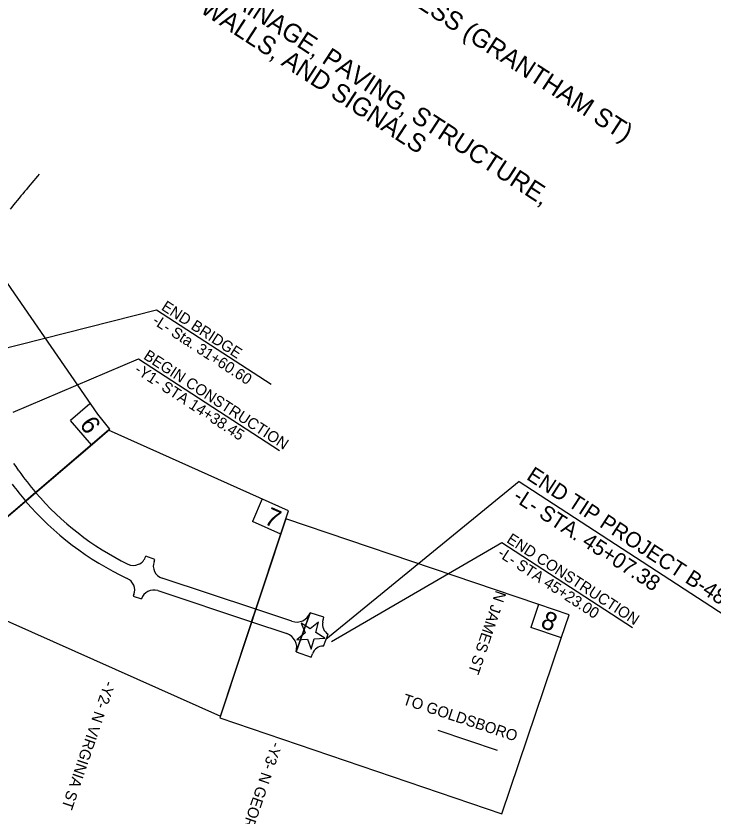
# Model space of a CAD drawing. Extents: x 2291197 to 2302790, y 592892 to 604246.
# Drawn here: x 2298300 to 2300199, y 598987 to 601165 of the extents above; entities that cross this region are included whole.
import ezdxf

# ---------------------------------------------------------------- set-up
doc = ezdxf.new("R2010")
doc.units = 0
for name, color, linetype in [('Exist Railroads Standard Gauge', 7, 'Continuous'), ('Prop DSN Text', 7, 'Continuous'), ('Prop Horizontal Alignment Station Label', 7, 'Continuous'), ('Prop RDY Traffic Signal CELL', 7, 'Continuous'), ('Prop Shade Light', 7, 'Continuous'), ('Sheet Data Field CELL', 7, 'Continuous')]:
    doc.layers.add(name, color=color, linetype=linetype)

msp = doc.modelspace()

# ---------------------------------------------------------------- linework, layer by layer
at = {"layer": 'Exist Railroads Standard Gauge'}
msp.add_arc((2302270.8, 597407.9), 5131.8, 139.5841, 140.9746, dxfattribs=at)
at = {"layer": 'Prop DSN Text'}
for p, q in [((2298501.3, 600109.3), (2298448.5, 600064.3)), ((2298505.6, 599997.3), (2298448.5, 600064.3)), ((2298971.3, 599850.2), (2298944.2, 599789.3)), ((2299021.6, 599754.7), (2298944.2, 599789.3)), ((2299723.9, 599562.7), (2299702.7, 599500.3)), ((2299786, 599472), (2299702.7, 599500.3)), ((2299611.7, 599164.8), (2299450, 599220))]:
    msp.add_line(p, q, dxfattribs=at)
for points in [[(2297647.4, 600347.7), (2298116.9, 599666), (2298116.9, 599666), (2298502, 599994.3), (2298556.3, 600040.5), (2298523, 600081.3), (2298287.2, 600423.6), (2298114.3, 600674.7)], [(2298166.7, 599708.4), (2298114.1, 599590.5), (2298857, 599258.9), (2299007.3, 599711.6), (2299042.7, 599818.3), (2298552.3, 600037.2)], [(2299035.5, 599796.5), (2298855.4, 599254), (2299623.4, 598993.2), (2299785.7, 599471.3), (2299807.2, 599534.4), (2299807.5, 599535), (2299721.9, 599563.3)]]:
    msp.add_lwpolyline(points, close=True, dxfattribs=at)
at = {"layer": 'Prop Horizontal Alignment Station Label'}
for p, q in [((2298085.2, 600214), (2298683, 600365.2)), ((2298683, 600365.2), (2298995, 600162.4)), ((2298292.2, 600086.9), (2298634.3, 600231.7)), ((2298634.3, 600231.7), (2299018.2, 599982.1)), ((2299671.3, 599897.4), (2299144.7, 599467.3)), ((2299671.3, 599897.4), (2300373.2, 599441.1)), ((2299159.6, 599462.4), (2299623.6, 599731.9)), ((2299623.6, 599731.9), (2299979.9, 599500.3))]:
    msp.add_line(p, q, dxfattribs=at)
at = {"layer": 'Prop RDY Traffic Signal CELL'}
msp.add_lwpolyline([(2299087.9, 599485.3), (2299065.3, 599467), (2299094.3, 599468.5), (2299104.7, 599441.4), (2299112.2, 599469.5), (2299141.2, 599471), (2299116.9, 599486.8), (2299124.4, 599514.8), (2299101.8, 599496.6), (2299077.4, 599512.4), (2299087.9, 599485.3)], dxfattribs=at)
at = {"layer": 'Prop Shade Light'}
for p, q in [((2298353.8, 599867.9), (2298326.4, 599844.6)), ((2298326.4, 599844.6), (2298353.8, 599867.9)), ((2298678.4, 599685.1), (2298653.9, 599694.2)), ((2298676.5, 599679.9), (2298678.4, 599685.1)), ((2298953.6, 599549.7), (2298698.2, 599634.5)), ((2298686.3, 599600.5), (2298942.3, 599515.6)), ((2298621.5, 599590.1), (2298619.9, 599585.7)), ((2298619.9, 599585.7), (2298642, 599578.1)), ((2298953.6, 599549.7), (2298942.3, 599515.6)), ((2298942.3, 599515.6), (2298953.6, 599549.7)), ((2299052.1, 599517), (2298953.6, 599549.7)), ((2299139, 599527.9), (2299102, 599540.3)), ((2298942.3, 599515.6), (2299037.7, 599483.9)), ((2299137.8, 599449.3), (2299150.5, 599482.3)), ((2299063.1, 599433.6), (2299104.8, 599419.6))]:
    msp.add_line(p, q, dxfattribs=at)
for points in [[(2298308.4, 599926.7), (2298300.3, 599938.2), (2298294, 599947.2)], [(2299063.1, 599433.6), (2299082.9, 599487.9), (2299102, 599540.3)], [(2299102, 599540.3), (2299082.9, 599487.9), (2299063.1, 599433.6)], [(2299136.3, 599515.1), (2299136.2, 599517.6), (2299137.7, 599523.8), (2299139, 599527.9)], [(2299104.8, 599419.6), (2299105.2, 599420.8), (2299108.3, 599428.9)]]:
    msp.add_lwpolyline(points, dxfattribs=at)
for centre, radius, start, end in [((2298948.9, 600375.3), 782, 215.0027, 220.4465), ((2298948.9, 600375.3), 818, 216.3618, 220.4465), ((2298948.9, 600375.3), 782, 220.4465, 243.913), ((2298948.9, 600375.3), 818, 220.4465, 245.0159), ((2298620.4, 599704.4), 35, 243.913, 343.1077), ((2298709.3, 599667.7), 35, 159.5745, 251.6371), ((2298588.6, 599602.1), 35, 339.9741, 65.0159), ((2298675.3, 599567.3), 35, 71.6371, 162.1209), ((2299064.7, 599555), 40, 251.6371, 338.4837), ((2299165.5, 599508.3), 30, 166.9415, 240.0259), ((2299025.1, 599445.9), 40, 342.0312, 71.6371), ((2299136.7, 599419.3), 30, 87.8938, 161.4979)]:
    msp.add_arc(centre, radius, start, end, dxfattribs=at)

# ---------------------------------------------------------------- texts
at = {"layer": 'Prop DSN Text'}
for s, height, rotation, p in [('6', 50, 304.5541, (2298471.8, 600053.4)), ('7', 50, 335.8394, (2298973.4, 599784)), ('N JAMES ST', 30, 251.0842, (2299608.1, 599602.7)), ('8', 50, 335.8394, (2299726.3, 599502.6)), ('-Y2- N VIRGINIA ST', 30, 251.0842, (2298542.6, 599356.7)), ('TO GOLDSBORO', 30, 341.6917, (2299351.6, 599291.8)), ('-Y3- N GEORGE ST', 30, 251.0842, (2298997.5, 599190.6))]:
    msp.add_text(s, height=height, rotation=rotation, dxfattribs=at).set_placement(p)
at = {"layer": 'Prop Horizontal Alignment Station Label'}
for s, height, p in [('END BRIDGE', 30, (2298694, 600367)), ('-L- Sta. 31+60.60', 30, (2298669.5, 600329.2)), ('BEGIN CONSTRUCTION', 30, (2298645.4, 600233.4)), ('-Y1- STA 14+38.45', 30, (2298620.9, 600195.7)), ('END TIP PROJECT B-4838', 42, (2299688.5, 599905.4)), ('-L- STA. 45+07.38', 42, (2299651.3, 599848.2)), ('END CONSTRUCTION', 30, (2299634.6, 599733.6)), ('-L- STA 45+23.00', 30, (2299610.1, 599695.9))]:
    msp.add_text(s, height=height, rotation=326.9737, dxfattribs=at).set_placement(p)
at = {"layer": 'Sheet Data Field CELL'}
for s, p in [('BRIDGE #950020 ON US 70 BUSINESS (GRANTHAM ST)', (2298479.6, 601782.7)), ('GRADING, DRAINAGE, PAVING, STRUCTURE, ', (2298513.9, 601440.7)), ('RETAINING WALLS, AND SIGNALS', (2298478.1, 601385.7))]:
    msp.add_text(s, height=50, rotation=326.9737, dxfattribs=at).set_placement(p)

doc.saveas('drawing.dxf')
